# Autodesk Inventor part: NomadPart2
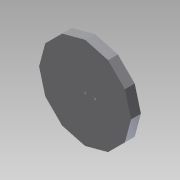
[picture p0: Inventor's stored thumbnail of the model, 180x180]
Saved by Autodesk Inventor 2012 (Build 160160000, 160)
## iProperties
Created: 2012-10
Part Number: NomadPart2
Material: Default
Document SubType Name: Modeling
Designer: TechShop Member
Density: 1 g/cm^3
Author: TechShop Member
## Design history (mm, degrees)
sketch "Sketch1"
  geometry: L1 (118.492, 0)-(102.617, -59.246); L2 (102.617, -59.246)-(59.246, -102.617); L3 (59.246, -102.617)-(0, -118.492); L4 (0, -118.492)-(-59.246, -102.617); L5 (-59.246, -102.617)-(-102.617, -59.246); L6 (-102.617, -59.246)-(-118.492, 0); L7 (-118.492, 0)-(-102.617, 59.246); L8 (-102.617, 59.246)-(-59.246, 102.617); L9 (-59.246, 102.617)-(0, 118.492); L10 (0, 118.492)-(59.246, 102.617); L11 (59.246, 102.617)-(102.617, 59.246); L12 (102.617, 59.246)-(118.492, 0); 2 further points
  constraints: 24 end point, 1 coincident, 25 other
  dimensions: "d0" = 236.98454 distance of L1.start L6.end
extrude "Extrusion1" new body sketch "Sketch1" distance "d1" = 25.4; taper "d2" = 0 deg
sketch "Sketch2"
  geometry: 2 further points
  constraints: 1 coincident
hole "Hole1" sketch "Sketch2" at (0, 0) diameter "d3" = 5.207; stored, may be unused: countersink angle "d7" = 82 deg, drill point angle "d9" = 118 deg; dims "d4" = 19.05, "d5" = 9.525, "d6" = 6.35, "d8" = 25.4
sketch "Sketch3"
  geometry: C1 r 2.603 at (0, 0) reference; 3 further points
  constraints: 2 coincident
hole "Hole2" sketch "Sketch3" at (0, 0), (25.4, 0) diameter "d10" = 5.207; stored, may be unused: countersink angle "d14" = 82 deg, drill point angle "d16" = 118 deg; dims "d11" = 19.05, "d12" = 9.525, "d13" = 6.35, "d15" = 25.4
body "Solid1"
